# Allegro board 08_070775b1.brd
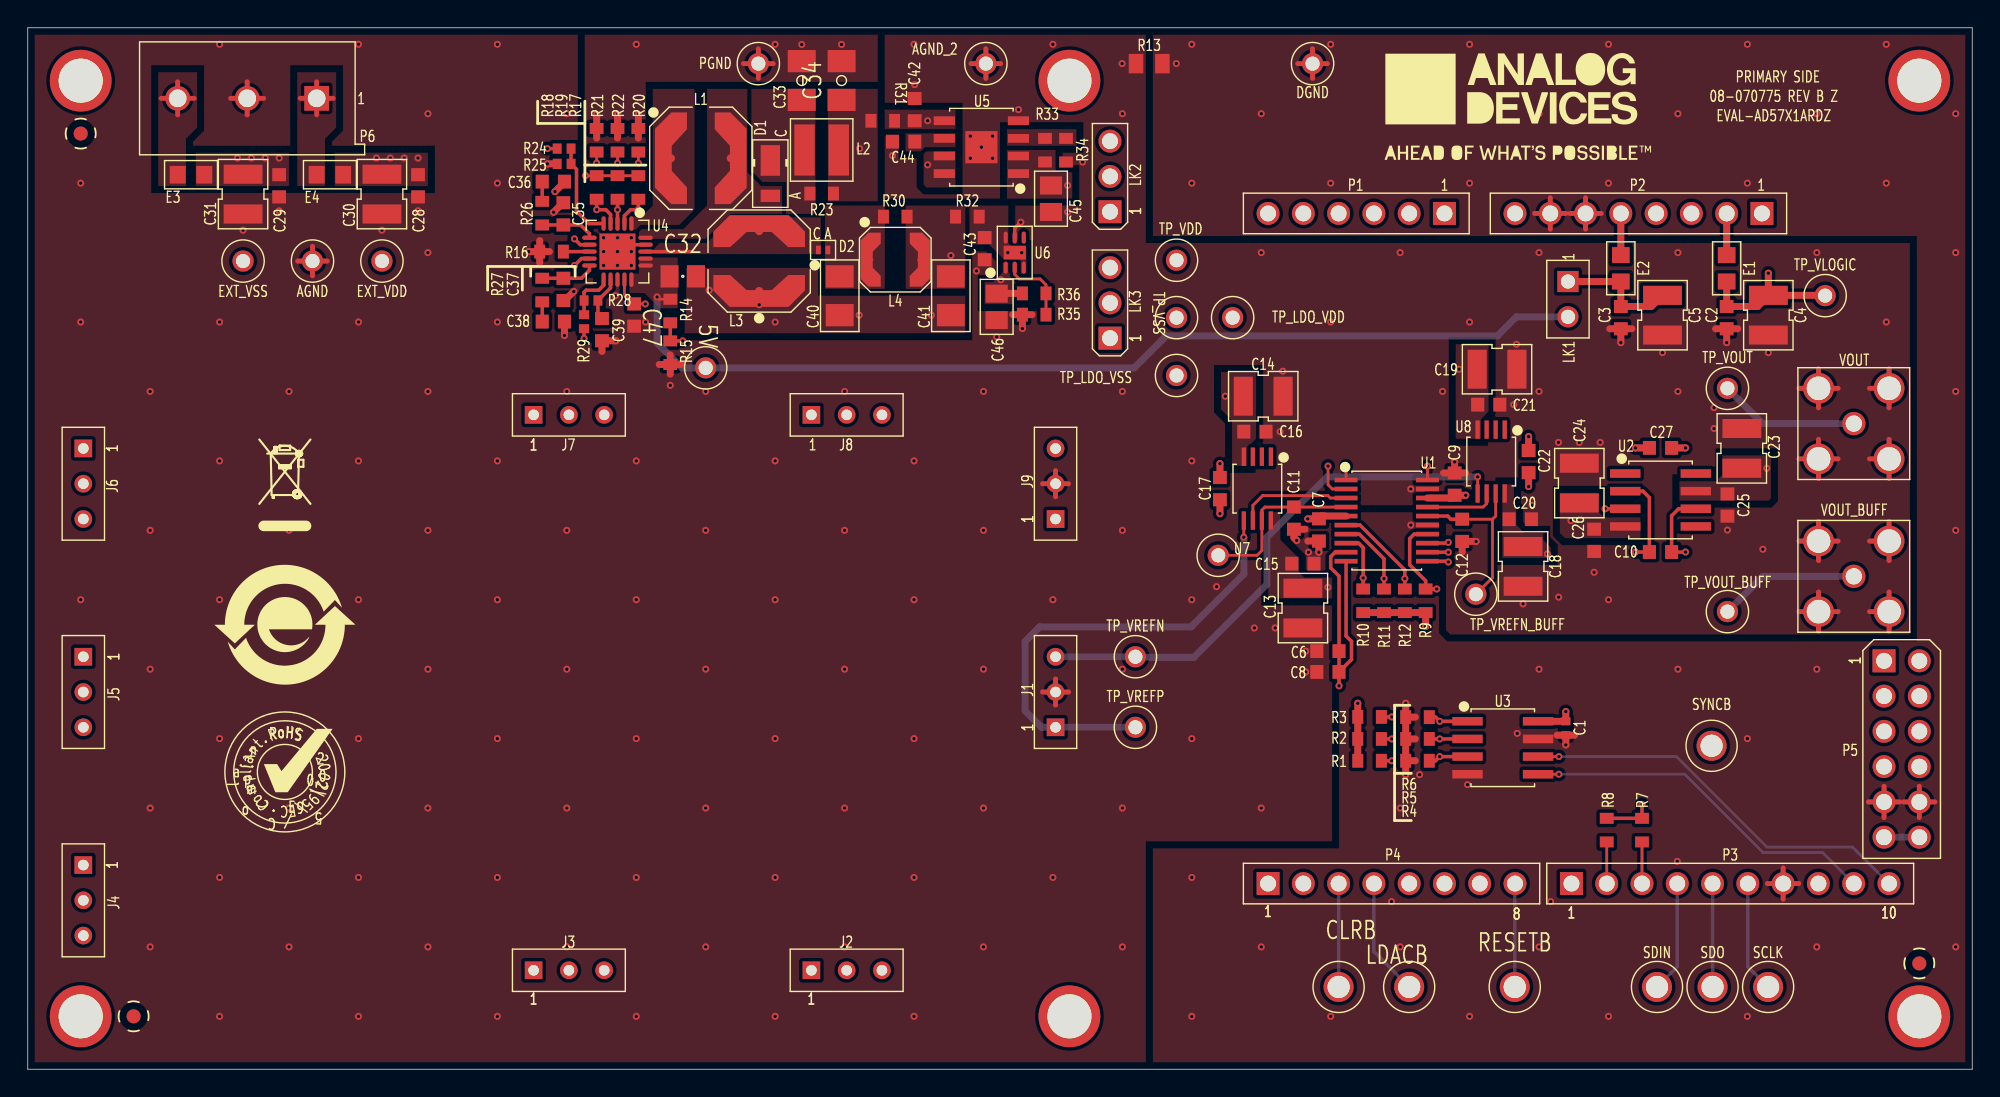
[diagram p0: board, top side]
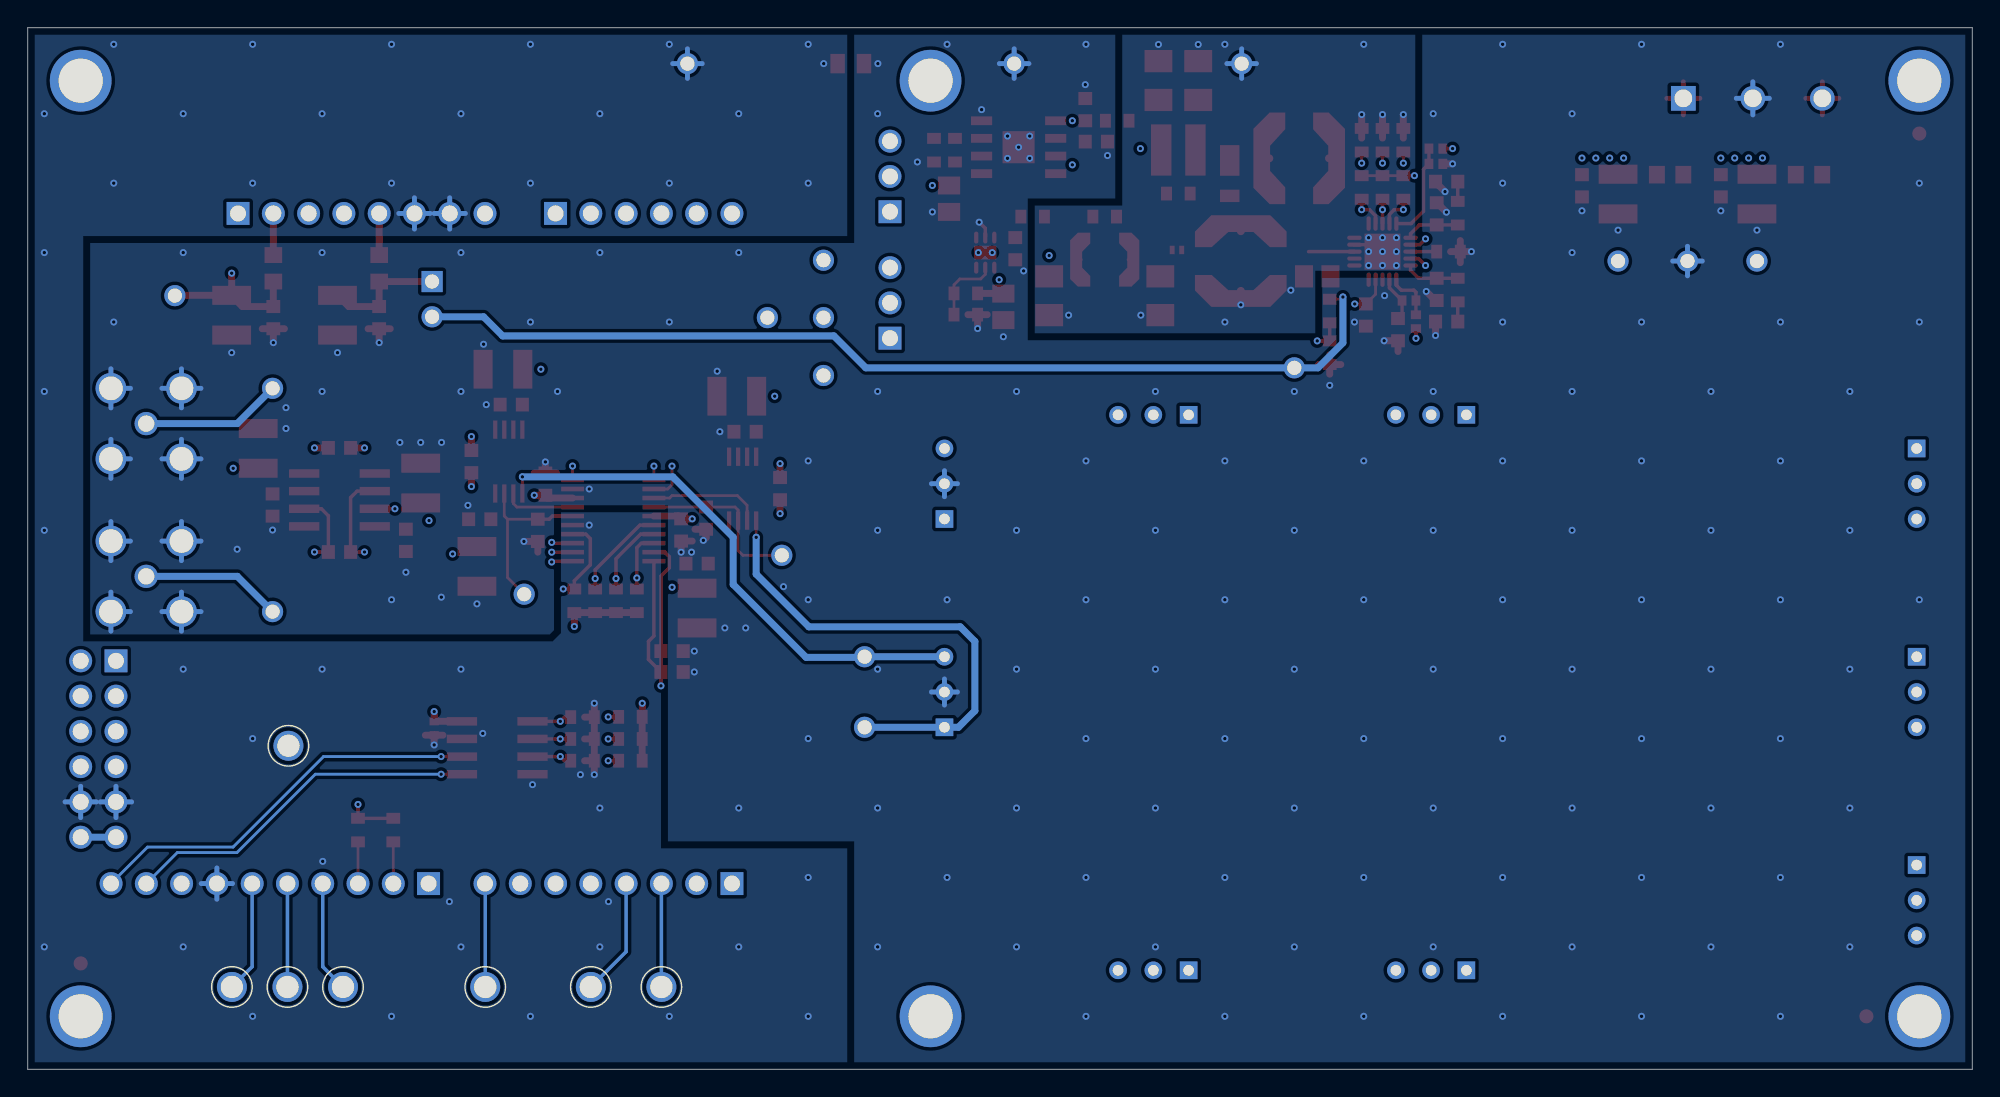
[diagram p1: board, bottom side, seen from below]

Outline 140 x 75 mm; copper layers: TOP, L2_GND, L3_SIG, L4_PWR, L5_GND, BOTTOM. Coordinates in mm from the lower left corner of the outline.
Outline path: 0,75 140,75 140,0 0,0 0,75

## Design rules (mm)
constraint set DEFAULT: 

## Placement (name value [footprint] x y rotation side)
C1  0.1uF  [C0402]  110.74 24.55 90 top
C2  0.1uF  [C0603]  122.32 54.12 270 top
C3  0.1uF  [C0603]  114.7 54.12 270 top
C4  10UF  [C1210H110]  125.32 54.3 270 top
C5  10UF  [C1210H110]  117.7 54.3 270 top
C6  0.1uF  [C0603]  93.61 30.11 180 top
C7  0.1uF  [C0603]  92.96 38.84 270 top
C8  0.1uF  [C0603]  93.61 28.61 180 top
C9  0.1uF  [C0603]  102.73 42.14 90 top
C10  10pF  [C0603]  117.56 37.25 180 top
C11  220pF  [C0603]  91.16 39.69 270 top
C12  220pF  [C0603]  103.28 38.81 270 top
C13  10UF  [C1210H110]  91.81 33.21 270 top
C14  10UF  [C1210H110]  88.95 48.47 180 top
C15  0.1uF  [C0603]  91.81 36.41 0 top
C16  0.1uF  [C0603]  88.36 45.91 180 top
C17  0.1uF  [C0603]  85.84 41.81 90 top
C18  10UF  [C1210H110]  107.66 36.21 270 top
C19  10UF  [C1210H110]  105.79 50.41 180 top
C20  0.1uF  [C0603]  107.46 39.61 0 top
C21  0.1uF  [C0603]  105.19 47.86 180 top
C22  0.1uF  [C0603]  108.06 43.76 90 top
C23  10UF  [C1210H110]  123.41 44.71 90 top
C24  10UF  [C1210H110]  111.71 42.21 270 top
C25  0.1uF  [C0603]  122.38 40.63 270 top
C26  0.1uF  [C0603]  112.78 38.09 90 top
C27  0.1uF  [C0603]  117.56 44.75 180 top
C28  0.1uF  [C0603]  28.1 63.62 270 top
C29  0.1uF  [C0603]  18.1 63.62 270 top
C30  10UF  [C1210H110]  25.5 63.02 270 top
C31  10UF  [C1210H110]  15.5 63.02 270 top
C32  10uF  [C0805H60]  47.16 57.1 0 top
C33  4.7uF  [C1206H71]  55.73 71.2 90 top
C34  4.7uF  [C1206H71]  58.59 71.2 90 top
C35  27pF  [C0603]  38.56 61.6 90 top
C36  0.022uF  [C0603]  37.84 63.92 0 top
C37  22pF  [C0603]  38.56 56.16 270 top
C38  0.082uF  [C0603]  37.84 53.84 0 top
C39  1UF  [C0603]  41.34 53.26 270 top
C40  2.2uF  [C1206H37]  58.46 55.7 270 top
C41  2.2uF  [C1206H37]  66.46 55.7 270 top
C42  1uF  [C0603]  63.86 69.11 90 top
C43  1uF  [C0603]  68.9 59.09 270 top
C44  0.01uF  [C0603]  63.06 66.8 180 top
C45  2.2uF  [C0805H53]  73.67 62.69 270 top
C46  2.2uF  [C0805H53]  69.76 54.9 270 top
C47  1uF  [C0603]  43.66 54.31 270 top
CLRB  WHT  [CNKEY5005-9TP]  94.38 5.93 0 top
D1  DFLS130-7  [POWERDI123]  53.46 64.5 270 top
D2  BAT54LPS  [DFN2_1X0_6]  57.26 59 0 top
E1  600OHM  [L0805H50]  122.32 57.68 270 top
E2  600OHM  [L0805H50]  114.7 57.68 270 top
E3  600OHM  [L0805H50]  11.75 64.42 0 top
E4  600OHM  [L0805H50]  21.75 64.42 0 top
J1  350-10-103-00-006000  [CNTHMHDR1X3L300W100H284]  74 24.62 90 top
J2  310-13-103-41-001000  [CNTHFHDR1X3L300W100H165]  56.42 7.12 0 top
J3  310-13-103-41-001000  [CNTHFHDR1X3L300W100H165]  36.42 7.12 0 top
J4  350-10-103-00-006000  [CNTHMHDR1X3L300W100H284]  4 14.71 270 top
J5  310-13-103-41-001000  [CNTHFHDR1X3L300W100H165]  4 29.7 270 top
J6  310-13-103-41-001000  [CNTHFHDR1X3L300W100H165]  4 44.71 270 top
J7  310-13-103-41-001000  [CNTHFHDR1X3L300W100H165]  36.42 47.12 0 top
J8  350-10-103-00-006000  [CNTHMHDR1X3L300W100H284]  56.42 47.12 0 top
J9  310-13-103-41-001000  [CNTHFHDR1X3L300W100H165]  74 39.62 90 top
L1  15uH  [LSMSQ236H138]  48.46 65.6 0 top
L2  1.5uH  [LSMSQ157H83]  57.16 66.2 0 top
L3  6.8uH  [LSMSQ236H138]  52.66 58.2 90 top
L4  2.2UH  [LSMSQ154H71_A]  62.46 58.3 0 top
LDACB  WHT  [CNKEY5005-9TP]  99.46 5.93 0 top
LK1  69157-102HLF  [CNBERG69157-102]  110.89 56.73 270 top
LK2  TSW-103-08-G-S  [CNBERG1X3H205LD36]  77.92 61.76 90 top
LK3  TSW-103-08-G-S  [CNBERG1X3H205LD36]  77.92 52.65 90 top
NOREF  -  []  18.51 32.01 0 top
NOREF#2  -  []  134 13.37 180 top
NOREF#3  -  []  -10.17 228.03 0 top
NOREF#4  -  [unnamed#2]  75 3.81 0 top
NOREF#5  -  [unnamed#2]  3.81 3.81 0 top
NOREF#6  -  []  3.81 3.81 0 top
NOREF#7  -  []  -22.36 -50.33 0 top
NOREF#8  -  []  3.81 3.81 0 top
NOREF#9  -  [unnamed#2]  3.81 71.19 0 top
NOREF#10  -  []  140 0 90 top
NOREF#11  -  []  212.02 314.24 0 top
NOREF#12  -  []  0 75 0 top
NOREF#13  -  []  0 0 0 top
NOREF#14  -  []  15 -82 0 top
NOREF#15  -  []  76.75 90.75 0 top
NOREF#16  -  []  18.31 38.81 0 top
NOREF#17  -  []  15 -82 0 top
NOREF#18  -  []  36.42 47.12 180 top
NOREF#19  -  []  -22.36 -50.33 0 top
NOREF#20  -  [unnamed#2]  75 71.19 0 top
NOREF#21  -  []  140 0 0 top
NOREF#22  -  [unnamed#2]  3.81 67.38 0 top
NOREF#23  -  []  88.21 167.82 0 top
NOREF#24  -  []  -2.99 312.45 0 top
NOREF#25  -  []  76.21 73.31 0 top
NOREF#26  -  [unnamed#2]  136.19 71.19 0 top
NOREF#27  -  [unnamed#2]  136.19 7.62 0 top
NOREF#28  -  []  140 0 0 top
NOREF#29  -  []  18.51 21.41 0 top
NOREF#30  -  []  140 75 0 top
NOREF#31  -  [unnamed#2]  136.19 3.81 0 top
NOREF#32  -  []  107.31 69.31 0 top
NOREF#33  -  [unnamed#2]  7.62 3.81 0 top
P1  SSQ-106-03-G-S  [CNSAMTECSSQ-106-XX-X-S]  102 61.63 180 top
P2  SSQ-108-03-G-S  [CNSAMTECSSQ-108-XX-X-S]  124.86 61.63 180 top
P3  SSQ-110-03-G-S  [CNSAMTECSSQ-110-XX-X-S]  111.14 13.37 0 top
P4  SSQ-108-03-G-S  [CNSAMTECSSQ-108-XX-X-S]  89.3 13.37 0 top
P5  TSW-106-08-G-D  [CNHDR2X6H330LD35]  133.65 29.41 270 top
P6  8719  [CNKEYSTONE-8719]  20.8 69.92 180 top
R1  100K  [R0603]  96.61 22.21 0 top
R2  0  [R0603]  96.61 23.79 0 top
R3  0  [R0603]  96.61 25.37 0 top
R4  0  [R0603]  100.06 22.21 180 top
R5  100K  [R0603]  100.06 23.79 180 top
R6  100K  [R0603]  100.06 25.36 180 top
R7  0  [R0603]  116.22 17.22 90 top
R8  0  [R0603]  113.68 17.22 90 top
R9  10K  [R0603]  100.65 33.73 90 top
R10  10K  [R0603]  96.15 33.73 90 top
R11  10K  [R0603]  97.65 33.73 90 top
R12  10K  [R0603]  99.15 33.73 90 top
R13  0  [R0805]  80.74 72.42 0 top
R14  30.1K  [R0603]  46.26 54.6 90 top
R15  18.7K  [R0603]  46.26 51.6 90 top
R16  49.9K  [R0603]  37.71 58.88 0 top
R17  0  [R0603]  43.96 63.5 270 top
R18  0  [R0603]  40.96 63.5 270 top
R19  0  [R0603]  42.46 63.5 270 top
R20  0  [R0603]  43.96 66.9 90 top
R21  0  [R0603]  40.96 66.9 90 top
R22  0  [R0603]  42.46 66.9 90 top
R23  4.7  [R0603]  57.16 63.06 0 top
R24  63.4K  [R0402]  38.62 66.3 180 top
R25  3.57K  [R0402]  38.62 65.2 180 top
R26  22K  [R0603]  37.04 61.65 90 top
R27  30.1K  [R0603]  37.04 56.11 270 top
R28  2.8K  [R0402]  40.55 55.36 180 top
R29  54.9K  [R0402]  40.05 53.84 270 top
R30  10  [R0603]  62.46 61.4 0 top
R31  10  [R0603]  61.56 68.31 0 top
R32  10  [R0603]  67.65 61.4 0 top
R33  105K  [R0603]  73.24 66.19 90 top
R34  10K  [R0603]  74.75 66.19 270 top
R35  10K  [R0603]  72.46 54.34 0 top
R36  105K  [R0603]  72.46 55.87 180 top
RESETB  WHT  [CNKEY5005-9TP]  107.06 5.93 0 top
SCLK  WHT  [CNKEY5005-9TP]  125.3 5.93 0 top
SDIN  WHT  [CNKEY5005-9TP]  117.3 5.93 0 top
SDO  WHT  [CNKEY5005-9TP]  121.3 5.93 0 top
SYNCB  WHT  [CNKEY5005-9TP]  121.23 23.29 0 top
TP_5V  RED  [CNKEY5001TP]  48.81 50.51 0 top
TP_AGND  BLK  [CNKEY5001TP]  20.5 58.2 0 top
TP_AGND2  BLK  [CNKEY5001TP]  68.98 72.42 0 top
TP_DGND  BLK  [CNKEY5001TP]  92.5 72.42 0 top
TP_EXT_VDD  RED  [CNKEY5001TP]  25.5 58.2 0 top
TP_EXT_VSS  RED  [CNKEY5001TP]  15.5 58.2 0 top
TP_LDO_VDD  RED  [CNKEY5001TP]  86.75 54.12 0 top
TP_LDO_VSS  RED  [CNKEY5001TP]  82.71 49.96 0 top
TP_PGND  BLK  [CNKEY5001TP]  52.6 72.42 0 top
TP_VDD  RED  [CNKEY5001TP]  82.71 58.26 0 top
TP_VLOGIC  RED  [CNKEY5001TP]  129.41 55.71 0 top
TP_VOUT  RED  [CNKEY5001TP]  122.38 49.04 0 top
TP_VOUT_BUFF  RED  [CNKEY5001TP]  122.38 32.95 0 top
TP_VREFN  RED  [CNKEY5001TP]  79.75 29.7 0 top
TP_VREFN_BUFF  RED  [CNKEY5001TP]  104.26 34.21 0 top
TP_VREFP  RED  [CNKEY5001TP]  79.75 24.62 0 top
TP_VREFP_BUFF  RED  [CNKEY5001TP]  85.71 37.01 0 top
TP_VSS  RED  [CNKEY5001TP]  82.71 54.12 0 top
U1  AD5781BRUZ  [TSSOP20]  97.85 39.51 270 top
U2  AD8675ARZ  [SO8]  117.56 41 270 top
U3  24AA32A-I/SN  [SO8]  106.2 23.15 270 top
U4  ADP5070ACPZ-R7  [QFN20_4X4_PAD2_6X2_6]  42.46 58.88 180 top
U5  ADP7118ARDZ  [SO8NB-PAD2_3X2_3]  68.66 66.4 90 top
U6  ADP7182ACPZN  [DFN6_2X2_PAD1_6X1]  71.06 58.81 0 top
U7  AD8676BRMZ  [MSOP8]  88.53 41.81 180 top
U8  AD8676BRMZ  [MSOP8]  105.37 43.76 180 top
VOUT  131-3701-261  [CNJOHNSON131-3701-261]  131.47 46.5 0 top
VOUT_BUFF  131-3701-261  [CNJOHNSON131-3701-261]  131.47 35.49 0 top

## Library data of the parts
C1 = CAP: User Part Number: UPN; Tolerance: 10; alternate symbols: (C0402); part number: CAP_SM-0.1UF,16V,10,E028141,C0402; tolerance: 10
C2 C3 C6-C9 C28 C29 = CAP: User Part Number: UPN; Tolerance: 10; alternate symbols: (C0603); part number: CAP_SM-0.1UF,16V,10,E015036,C0603; tolerance: 10
C4 C5 C13 C14 C18 C19 C23 C24 C30 C31 = CAP: Tolerance: 10; User Part Number: UPN; alternate symbols: (C1210H110); part number: CAP_SM-10UF,75V,10,E054052,C1210H110; tolerance: 10
C10 = CAP: User Part Number: UPN; Tolerance: 5; alternate symbols: (C0603); part number: CAP_SM-10PF,50V,5,E031564,C0603; tolerance: 5
C11 C12 = CAP: User Part Number: UPN; Tolerance: 5; alternate symbols: (C0603); part number: CAP_SM-220PF,50V,5,E000417,C0603; tolerance: 5
C15-C17 C20-C22 C25-C27 = CAP: User Part Number: UPN; Tolerance: 10; alternate symbols: (C0603); part number: CAP_SM-0.1UF,25V,10,E007204,C0603; tolerance: 10
C32 = CAP: Tolerance: 10; User Part Number: UPN; alternate symbols: (C0805H60); part number: CAP_SM-10UF,25V,10,E026259,C0805H60; tolerance: 10
C33 C34 = CAP: Tolerance: 10; User Part Number: UPN; alternate symbols: (C1206H71); part number: CAP_SM-4.7UF,50V,10,E038262,C1206H71; tolerance: 10
C35 = CAP: User Part Number: UPN; Tolerance: 5; alternate symbols: (C0603); part number: CAP_SM-27PF,50V,5,E000395,C0603; tolerance: 5
C36 = CAP: User Part Number: UPN; Tolerance: 10; alternate symbols: (C0603); part number: CAP_SM-0.022UF,16V,10,E000327,C0603; tolerance: 10
C37 = CAP: User Part Number: UPN; Tolerance: 5; alternate symbols: (C0603); part number: CAP_SM-22PF,50V,5,E000411,C0603; tolerance: 5
C38 = CAP: User Part Number: UPN; Tolerance: 10; alternate symbols: (C0603); part number: CAP_SM-0.082UF,16V,10,E028750,C0603; tolerance: 10
C39 = CAP: User Part Number: UPN; Tolerance: 20; alternate symbols: (C0603); part number: CAP_SM-1UF,10V,20,E042691,C0603; tolerance: 20
C40 C41 = CAP: Tolerance: 10; User Part Number: UPN; alternate symbols: (C1206H37); part number: CAP_SM-2.2UF,50V,10,E020593,C1206H37; tolerance: 10
C42 C43 = CAP: User Part Number: UPN; Tolerance: 10; alternate symbols: (C0603); part number: CAP_SM-1UF,16V,10,E020596,C0603; tolerance: 10
C44 = CAP: User Part Number: UPN; Tolerance: 10; alternate symbols: (C0603); part number: CAP_SM-0.01UF,50V,10,E015579,C0603; tolerance: 10
C45 C46 = CAP: Tolerance: 10; User Part Number: UPN; alternate symbols: (C0805H53); part number: CAP_SM-2.2UF,25V,10,E025703,C0805H53; tolerance: 10
C47 = CAP: User Part Number: UPN; Tolerance: 10; alternate symbols: (C0603); part number: CAP_SM-1UF,16V,10,E025399,C0603; tolerance: 10
CLRB LDACB RESETB SCLK SDIN SDO SYNCB = CNTP1P: Tolerance: N/A; User Part Number: UPN; alternate symbols: (CNKEY5005-9TP); part number: CNTP1P_TH-WHT,E025331,CNKEY5005-9TP; tolerance: N/A
D1 = DIOSCHOTTKY: User Part Number: UPN; Tolerance: N/A; alternate symbols: (POWERDI123); part number: DIOSCHOTTKY_SM-DFLS130-7,30V,N/A,E026485,POWERDI123; tolerance: N/A
D2 = DIOSCHOTTKY: Tolerance: N/A; User Part Number: UPN; alternate symbols: (DFN2_1X0_6); part number: DIOSCHOTTKY_SM-BAT54LPS,30V,N/A,E023691,DFN2_1X0_6; tolerance: N/A
E1-E4 = FERRITE: Tolerance: 25; User Part Number: UPN; alternate symbols: (L0805H50); part number: FERRITE_SM-600OHM,25,E013538,L0805H50; tolerance: 25
J1 J4 J8 = CN3P: User Part Number: UPN; Tolerance: N/A; alternate symbols: (CNTHMHDR1X3L300W100H284); part number: CN3P_TH-350-10-103-00-006000,E027762,CNTHMHDR1X3L300W100H284; tolerance: N/A
J2 J3 J5-J7 J9 = CN3P: User Part Number: UPN; Tolerance: N/A; alternate symbols: (CNTHFHDR1X3L300W100H165); part number: CN3P_TH-310-13-103-41-001000,E027752,CNTHFHDR1X3L300W100H165; tolerance: N/A
L1 = IND_SM-15UH,20,E019587,LSMSQ236H138-LSMSQ236H138: User Part Number: UPN; Tolerance: 20
L2 = IND: User Part Number: UPN; Tolerance: 20; alternate symbols: (LSMSQ157H83); part number: IND_SM-1.5UH,20,E017267,LSMSQ157H83; tolerance: 20
L3 = IND: User Part Number: UPN; Tolerance: 20; alternate symbols: (LSMSQ236H138); part number: IND_SM-6.8UH,20,E020918,LSMSQ236H138; tolerance: 20
L4 = IND: User Part Number: UPN; Tolerance: 20; alternate symbols: (LSMSQ154H71_A); part number: IND_SM-2.2UH,20,E024446,LSMSQ154H71_A; tolerance: 20
LK1 = CN2P: User Part Number: UPN; Tolerance: N/A; alternate symbols: (CNBERG69157-102); part number: CN2P_TH-69157-102HLF,E000791,CNBERG69157-102; tolerance: N/A
LK2 LK3 = CN3P: User Part Number: UPN; Tolerance: N/A; alternate symbols: (CNBERG1X3H205LD36); part number: CN3P_TH-TSW-103-08-G-S,E000812,CNBERG1X3H205LD36; tolerance: N/A
P1 = CN6P: User Part Number: UPN; Tolerance: N/A; alternate symbols: (CNSAMTECSSQ-106-XX-X-S); part number: CN6P_TH-SSQ-106-03-G-S,E020477,CNSAMTECSSQ-106-XX-X-S; tolerance: N/A
P2 P4 = CN8P_A: User Part Number: UPN; Tolerance: N/A; alternate symbols: (CNSAMTECSSQ-108-XX-X-S); part number: CN8P_A_TH-SSQ-108-03-G-S,E020478,CNSAMTECSSQ-108-XX-X-S; tolerance: N/A
P3 = CN10P: User Part Number: UPN; Tolerance: N/A; alternate symbols: (CNSAMTECSSQ-110-XX-X-S); part number: CN10P_TH-SSQ-110-03-G-S,E020479,CNSAMTECSSQ-110-XX-X-S; tolerance: N/A
P5 = CN12P_V3: Tolerance: N/A; User Part Number: UPN; alternate symbols: (CNHDR2X6H330LD35); part number: CN12P_V3_TH-TSW-106-08-G-D,E000735,CNHDR2X6H330LD35; tolerance: N/A
P6 = CN3P: Tolerance: N/A; User Part Number: UPN; alternate symbols: (CNKEYSTONE-8719); part number: CN3P_TH-8719,E023615,CNKEYSTONE-8719; tolerance: N/A
R1 R5 R6 = RES: User Part Number: UPN; Tolerance: 1; alternate symbols: (R0603); part number: RES_SM-100K,E017869,1/10W,1,R0603; tolerance: 1
R2-R4 = RES: User Part Number: UPN; Tolerance: 1; alternate symbols: (R0603); part number: RES_SM-0,E004207,1/16W,1,R0603; tolerance: 1
R7 R8 R17-R22 = RES: User Part Number: UPN; Tolerance: JUMPER; alternate symbols: (R0603); part number: RES_SM-0,E054377,1/10W,JUMPER,R0603; tolerance: JUMPER
R9-R12 = RES: User Part Number: UPN; Tolerance: 0.1; alternate symbols: (R0603); part number: RES_SM-10K,E020748,1/10W,0.1,R0603; tolerance: 0.1
R13 = RES: User Part Number: UPN; Tolerance: N/A; alternate symbols: (R0805); part number: RES_SM-0,E004449,1/8W,N/A,R0805; tolerance: N/A
R14 R27 = RES: User Part Number: UPN; Tolerance: 1; alternate symbols: (R0603); part number: RES_SM-30.1K,E011129,1/10W,1,R0603; tolerance: 1
R15 = RES: User Part Number: UPN; Tolerance: 1; alternate symbols: (R0603); part number: RES_SM-18.7K,E011248,1/10W,1,R0603; tolerance: 1
R16 = RES: User Part Number: UPN; Tolerance: 1; alternate symbols: (R0603); part number: RES_SM-49.9K,E015342,1/10W,1,R0603; tolerance: 1
R23 = RES: User Part Number: UPN; Tolerance: 1; alternate symbols: (R0603); part number: RES_SM-4.7,E003938,1/10W,1,R0603; tolerance: 1
R24 = RES: User Part Number: UPN; Tolerance: 1; alternate symbols: (R0402); part number: RES_SM-63.4K,E006803,1/10W,1,R0402; tolerance: 1
R25 = RES: User Part Number: UPN; Tolerance: 1; alternate symbols: (R0402); part number: RES_SM-3.57K,E007344,1/10W,1,R0402; tolerance: 1
R26 = RES: User Part Number: UPN; Tolerance: 0.1; alternate symbols: (R0603); part number: RES_SM-22K,E057217,1/5W,0.1,R0603; tolerance: 0.1
R28 = RES: User Part Number: UPN; Tolerance: 1; alternate symbols: (R0402); part number: RES_SM-2.8K,E012202,1/10W,1,R0402; tolerance: 1
R29 = RES: User Part Number: UPN; Tolerance: 1; alternate symbols: (R0402); part number: RES_SM-54.9K,E023190,1/10W,1,R0402; tolerance: 1
R30-R32 = RES: User Part Number: UPN; Tolerance: 1; alternate symbols: (R0603); part number: RES_SM-10,E003666,1/10W,1,R0603; tolerance: 1
R33 R36 = RES: User Part Number: UPN; Tolerance: 1; alternate symbols: (R0603); part number: RES_SM-105K,E019711,1/10W,1,R0603; tolerance: 1
R34 R35 = RES: User Part Number: UPN; Tolerance: 1; alternate symbols: (R0603); part number: RES_SM-10K,E003671,1/10W,1,R0603; tolerance: 1
TP_5V TP_EXT_VDD TP_EXT_VSS TP_LDO_VDD TP_LDO_VSS TP_VDD TP_VLOGIC TP_VOUT TP_VOUT_BUFF TP_VREFN TP_VREFN_BUFF TP_VREFP TP_VREFP_BUFF TP_VSS = CNTP1P: Tolerance: N/A; User Part Number: UPN; alternate symbols: (CNKEY5001TP); part number: CNTP1P_TH-RED,E016323,CNKEY5001TP; tolerance: N/A
TP_AGND TP_AGND2 TP_DGND TP_PGND = CNTP1P: Tolerance: N/A; User Part Number: UPN; alternate symbols: (CNKEY5001TP); part number: CNTP1P_TH-BLK,E005347,CNKEY5001TP; tolerance: N/A
U1 = AD5781: Tolerance: N/A; User Part Number: UPN; alternate symbols: (TSSOP20); part number: AD5781_SM-AD5781BRUZ,E016086,TSSOP20; tolerance: N/A
U2 = AD8675: Tolerance: N/A; User Part Number: UPN; alternate symbols: (SO8); part number: AD8675_SM-AD8675ARZ,E005913,SO8; tolerance: N/A
U3 = IC24XX32A_V2: Tolerance: N/A; User Part Number: UPN; alternate symbols: (SO8); part number: IC24XX32A_V2_SM-24AA32A-I/SN,E034913,SO8; tolerance: N/A
U4 = ADP5070: User Part Number: UPN; Tolerance: N/A; alternate symbols: (QFN20_4X4_PAD2_6X2_6); part number: ADP5070_SM-ADP5070ACPZ-R7,E017319,QFN20_4X4_PAD2_6X2_6; tolerance: N/A
U5 = ADP7118_V3: Tolerance: N/A; User Part Number: UPN; alternate symbols: (SO8NB-PAD2_3X2_3); part number: ADP7118_V3_SM-ADP7118ARDZ,E020780,SO8NB-PAD2_3X2_3; tolerance: N/A
U6 = ADP7182_V5: User Part Number: UPN; Tolerance: N/A; alternate symbols: (DFN6_2X2_PAD1_6X1); part number: ADP7182_V5_SM-ADP7182ACPZN,E024308,DFN6_2X2_PAD1_6X1; tolerance: N/A
U7 U8 = ADOPAMP2: Tolerance: N/A; User Part Number: UPN; alternate symbols: (MSOP8); part number: ADOPAMP2_SM-AD8676BRMZ,E015333,MSOP8; tolerance: N/A
VOUT VOUT_BUFF = CNBNC5P: Tolerance: N/A; User Part Number: UPN; alternate symbols: (CNJOHNSON131-3701-261); part number: CNBNC5P_TH-131-3701-261,E012123,CNJOHNSON131-3701-261; tolerance: N/A

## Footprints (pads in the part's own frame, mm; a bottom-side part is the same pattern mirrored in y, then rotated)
C0402
  rect 0.584x0.66 smd: 1(-0.5,0) 2(0.5,0)
C0603
  rect 0.94x0.991 smd: 1(-0.8,0) 2(0.8,0)
C0805H53
  rect 1.295x1.6 smd: 1(-0.953,0) 2(0.953,0)
C0805H60
  rect 1.295x1.6 smd: 1(-0.953,0) 2(0.953,0)
C1206H37
  rect 1.6x2.007 smd: 1(-1.397,0) 2(1.397,0)
C1206H71
  rect 1.6x2.007 smd: 1(-1.397,0) 2(1.397,0)
C1210H110
  rect 1.372x2.794 smd: 1(-1.431,0) 2(1.431,0)
CNBERG1X3H205LD36
  rect 1.651x1.651 hole 1.143: 1(0,0)
  round 1.651 hole 1.143: 2(2.54,0) 3(5.08,0)
CNBERG69157-102
  rect 1.524x1.524 hole 1.016: 1(0,0)
  round 1.524 hole 1.016: 2(2.54,0)
CNHDR2X6H330LD35
  rect 1.651x1.651 hole 1.143: 1(0,0)
  round 1.651 hole 1.143: 2(2.54,0) 3(5.08,0) 4(7.62,0) 5(10.16,0) 6(12.7,0) 7(0,2.54) 8(2.54,2.54) 9(5.08,2.54) 10(7.62,2.54) 11(10.16,2.54) 12(12.7,2.54)
CNJOHNSON131-3701-261
  round 1.676 hole 1.168: 1(0,0)
  round 2.21 hole 1.702: 2(-2.54,2.54) 3(2.54,2.54) 4(2.54,-2.54) 5(-2.54,-2.54)
CNKEY5001TP
  round 1.524 hole 1.016: 1(0,0)
CNKEY5005-9TP
  round 2.159 hole 1.6: 1(0,0)
CNKEYSTONE-8719
  rect 1.778x1.778 hole 1.27: 1(0,0)
  round 1.778 hole 1.27: 2(5.004,0) 3(10.008,0)
CNSAMTECSSQ-106-XX-X-S
  rect 1.651x1.651 hole 1.143: 1(0,0)
  round 1.651 hole 1.143: 2(2.54,0) 3(5.08,0) 4(7.62,0) 5(10.16,0) 6(12.7,0)
CNSAMTECSSQ-108-XX-X-S
  rect 1.651x1.651 hole 1.143: 1(0,0)
  round 1.651 hole 1.143: 2(2.54,0) 3(5.08,0) 4(7.62,0) 5(10.16,0) 6(12.7,0) 7(15.24,0) 8(17.78,0)
CNSAMTECSSQ-110-XX-X-S
  rect 1.651x1.651 hole 1.143: 1(0,0)
  round 1.651 hole 1.143: 2(2.54,0) 3(5.08,0) 4(7.62,0) 5(10.16,0) 6(12.7,0) 7(15.24,0) 8(17.78,0) 9(20.32,0) 10(22.86,0)
CNTHFHDR1X3L300W100H165
  rect 1.27x1.27 hole 0.762: 1(0,0)
  round 1.27 hole 0.762: 2(2.54,0) 3(5.08,0)
CNTHMHDR1X3L300W100H284
  rect 1.27x1.27 hole 0.762: 1(0,0)
  round 1.27 hole 0.762: 2(2.54,0) 3(5.08,0)
DFN2_1X0_6
  rect 0.356x0.61 smd: A(0.34,0) C(-0.34,0)
DFN6_2X2_PAD1_6X1
  oval 0.305x0.864 smd: 1(-0.65,-1.082) 2(0,-1.082) 3(0.65,-1.082) 4(0.65,1.082) 5(0,1.082) 6(-0.65,1.082)
  rect 1.6x0.991 smd: PAD(0,0)
L0805H50
  rect 1.143x1.27 smd: 1(-0.953,0) 2(0.953,0)
LSMSQ154H71_A
  custom 0.362x0.362 smd: 1(-1.765,0) 2(1.765,0)
LSMSQ157H83
  rect 1.473x3.683 smd: 1(-1.232,0) 2(1.232,0)
LSMSQ236H138
  custom 0.575x0.575 smd: 1(-2.151,0) 2(2.151,0)
MSOP8
  rect 0.305x1.321 smd: 1(-0.975,-2.3) 2(-0.325,-2.3) 3(0.325,-2.3) 4(0.975,-2.3) 5(0.975,2.3) 6(0.325,2.3) 7(-0.325,2.3) 8(-0.975,2.3)
POWERDI123
  rect 0.889x1.397 smd: A(1.605,0)
  rect 2.21x1.397 smd: C(-0.945,0)
QFN20_4X4_PAD2_6X2_6
  oval 0.305x1.041 smd: 1(-1,-2.019) 2(-0.5,-2.019) 3(0,-2.019) 4(0.5,-2.019) 5(1,-2.019) 11(1,2.019) 12(0.5,2.019) 13(0,2.019) 14(-0.5,2.019) 15(-1,2.019)
  oval 1.041x0.305 smd: 6(2.019,-1) 7(2.019,-0.5) 8(2.019,0) 9(2.019,0.5) 10(2.019,1) 16(-2.019,1) 17(-2.019,0.5) 18(-2.019,0) 19(-2.019,-0.5) 20(-2.019,-1)
  rect 2.591x2.591 smd: PAD(0,0)
R0402
  rect 0.635x0.737 smd: 1(-0.5,0) 2(0.5,0)
R0603
  rect 0.787x0.991 smd: 1(-0.85,0) 2(0.85,0)
R0805
  rect 1.041x1.397 smd: 1(-0.95,0) 2(0.95,0)
SO8
  rect 0.61x2.184 smd: 1(-1.905,-2.54) 2(-0.635,-2.54) 3(0.635,-2.54) 4(1.905,-2.54) 5(1.905,2.54) 6(0.635,2.54) 7(-0.635,2.54) 8(-1.905,2.54)
SO8NB-PAD2_3X2_3
  rect 0.635x1.524 smd: 1(-1.905,-2.667) 2(-0.635,-2.667) 3(0.635,-2.667) 4(1.905,-2.667) 5(1.905,2.667) 6(0.635,2.667) 7(-0.635,2.667) 8(-1.905,2.667)
  rect 2.311x2.311 smd: PAD(0,0)
TSSOP20
  rect 0.33x1.651 smd: 1(-2.925,-2.93) 2(-2.275,-2.93) 3(-1.625,-2.93) 4(-0.975,-2.93) 5(-0.325,-2.93) 6(0.325,-2.93) 7(0.975,-2.93) 8(1.625,-2.93) 9(2.275,-2.93) 10(2.925,-2.93) 11(2.925,2.93) 12(2.275,2.93) 13(1.625,2.93) 14(0.975,2.93) 15(0.325,2.93) 16(-0.325,2.93) 17(-0.975,2.93) 18(-1.625,2.93) 19(-2.275,2.93) 20(-2.925,2.93)
unnamed#2
  round 4.445 hole 3.175 unplated: (0,0)

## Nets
AGND: C2.2(N2) C3.2(N2) C4.2(N2) C5.2(N2) C6.2(N2) C7.2(N2) C8.2(N2) C9.2(N2) C11.2(N2) C12.2(N2) C13.2(N2) C14.1 C15.2(N2) C16.1 C18.2(N2) C19.1 C20.2(N2) C21.1 C23.2(N2) C24.1 C25.2(N2) C26.1 C28.2(N2) C29.2(N2) C30.2(N2) C31.2(N2) C32.2(N2) C33.2(N2) C34.2(N2) C35.2(N2) C36.2(N2) C37.2(N2) C38.2(N2) C39.2(N2) C40.2(N2) C41.2(N2) C42.2(N2) C43.2(N2) C44.2(N2) C45.2(N2) C46.2(N2) C47.2(N2) J1.2 J9.2 L3.1 P6.2 R13.1 R15.1 R16.1 R20.2(N2) R21.2(N2) R22.2(N2) R25.2(N2) R34.2(N2) R35.1 TP_AGND.1(N1) TP_AGND2.1(N1) TP_PGND.1(N1) U1.19 U4.13 U4.19 U4.PAD U5.4 U5.PAD U6.5 VOUT.2 VOUT.3 VOUT.4 VOUT.5(SH4) VOUT_BUFF.2 VOUT_BUFF.3 VOUT_BUFF.4 VOUT_BUFF.5(SH4)
DGND: C1.1 P2.6 P2.7 P3.7 P5.5 P5.11 R4.2(N2) R5.2(N2) R6.2(N2) R13.2(N2) TP_DGND.1(N1) U1.15 U3.4 U3.7(WP)
VDD: C7.1 C13.1 C15.1 C17.1 C18.1 C20.1 C22.1 C23.1 C25.1 C27.1 J9.1 LK2.2 TP_VDD.1(N1) U1.5 U2.7 U7.8 U8.8
VSS: C9.1 C14.2(N2) C16.2(N2) C17.2(N2) C19.2(N2) C21.2(N2) C22.2(N2) C24.2(N2) C26.2(N2) C27.2(N2) J9.3(N3) LK3.2 TP_VSS.1(N1) U1.18(VSS) U2.4(V-) U7.4(V-) U8.4(V-)
ARD_5V: C32.1 LK1.2(N2) R14.2(N2) TP_5V.1(N1) U4.15 U4.16 U4.17
ARD_CLRB: CLRB.1(N1) P4.3 P5.9 R11.2(N2) U1.7
ARD_LDACB: LDACB.1(N1) P4.4 P5.7 R10.2(N2) U1.8
ARD_RESETB: P4.8(N8) P5.8 R12.2(N2) RESETB.1(N1) U1.6
ARD_SCL: P3.10 U3.6
ARD_SCLK: P3.6 P5.4 SCLK.1(N1) U1.13
ARD_SDA: P3.9(N9) U3.5
ARD_SDIN: P3.4 P5.2 SDIN.1(N1) U1.12
ARD_SDO: P3.5 P5.3 SDO.1(N1) U1.11
ARD_SYNCB: P5.1 R7.2(N2) R8.2(N2) R9.2(N2) SYNCB.1(N1) U1.14
ARD_VLOGIC: C1.2(N2) C2.1 C4.1 C6.1 C8.1 E1.2(N2) P5.6 P5.12(VCC2) R1.1 R2.1 R3.1 R9.1 R10.1 R11.1 R12.1 TP_VLOGIC.1(N1) U1.9 U1.10 U3.8
DAC_INV: C10.2(N2) U1.1 U2.2
DAC_VOUT: C10.1 TP_VOUT_BUFF.1(N1) U1.20 U2.6 VOUT_BUFF.1
EXT_VDD: C28.1 C30.1 E4.2(N2) LK2.3(N3) TP_EXT_VDD.1(N1)
EXT_VSS: C29.1 C31.1 E3.2(N2) LK3.3(N3) TP_EXT_VSS.1(N1)
LDO_VDD: C45.1 LK2.1 R33.1 TP_LDO_VDD.1(N1) U5.1 U5.2(VOUT2)
LDO_VSS: C46.1 LK3.1 R36.2(N2) TP_LDO_VSS.1(N1) U6.1(VOUT)
REF_VREFN: J1.3(N3) TP_VREFN.1(N1) U8.5
REF_VREFP: J1.1 TP_VREFP.1(N1) U7.5
UNNAMED_3_CAP_I64_N1: C3.1 C5.1 E2.2(N2) LK1.1
UNNAMED_3_CN8PA_I4_N2: E1.1 P2.2
UNNAMED_3_CN8PA_I4_N5: E2.1 P2.5
UNNAMED_3_CN10P_I1_N2: P3.2 R8.1
UNNAMED_3_CN10P_I1_N3: P3.3 R7.1
UNNAMED_3_IC24XX32AV2_I22_A0: R3.2(N2) R6.1 U3.1
UNNAMED_3_IC24XX32AV2_I22_A1: R2.2(N2) R5.1 U3.2
UNNAMED_3_IC24XX32AV2_I22_A2: R1.2(N2) R4.1 U3.3
UNNAMED_4_AD5781_I1_VOUT: TP_VOUT.1(N1) U1.2 U2.3 VOUT.1
UNNAMED_5_ADP5070_I35_COMP1: C35.1 R26.1 U4.6
UNNAMED_5_ADP5070_I35_COMP2: C37.1 R27.1 U4.10
UNNAMED_5_ADP5070_I35_EN1: R14.1 R15.2(N2) U4.7 U4.9
UNNAMED_5_ADP5070_I35_FB1: R24.1 R25.1 U4.5
UNNAMED_5_ADP5070_I35_FB2: R28.2(N2) R29.1 U4.11
UNNAMED_5_ADP5070_I35_INBK: L1.1 U4.1
UNNAMED_5_ADP5070_I35_SEQ: R19.2(N2) R22.1 U4.3
UNNAMED_5_ADP5070_I35_SLEW: R18.2(N2) R21.1 U4.4
UNNAMED_5_ADP5070_I35_SS: R16.2(N2) U4.8
UNNAMED_5_ADP5070_I35_SW1: D1.A(P) L1.2(N2) U4.20
UNNAMED_5_ADP5070_I35_SW2: D2.C L3.2(N2) U4.18
UNNAMED_5_ADP5070_I35_SYNC: R17.2(N2) R20.1 U4.2
UNNAMED_5_ADP5070_I35_VREF: C39.1 R28.1 U4.12
UNNAMED_5_ADP5070_I35_VREG: C47.1 R17.1 R18.1 R19.1 U4.14(VREG)
UNNAMED_5_ADP7118V3_I94_EN: C42.1 R31.2(N2) U5.5 U5.7 U5.8
UNNAMED_5_ADP7118V3_I94_SENSE: R33.2(N2) R34.1 U5.3
UNNAMED_5_ADP7118V3_I94_SS: C44.1 U5.6
UNNAMED_5_ADP7182V5_I95_ADJ: R35.2(N2) R36.1 U6.2
UNNAMED_5_ADP7182V5_I95_EN: C43.1 R32.2(N2) U6.3 U6.6 U6.PAD
UNNAMED_5_CAP_I60_N1: C33.1 D1.C L2.1 R23.1
UNNAMED_5_CAP_I61_N1: C34.1 L2.2(N2) R23.2(N2) R24.2(N2) R31.1
UNNAMED_5_CAP_I69_N1: C36.1 R26.2(N2)
UNNAMED_5_CAP_I73_N1: C38.1 R27.2(N2)
UNNAMED_5_CAP_I79_N1: C41.1 L4.2(N2) R29.2(N2) R30.2(N2) R32.1
UNNAMED_5_CAP_I80_N1: C40.1 D2.A(P) L4.1 R30.1
UNNAMED_5_CN3P_I3_N1: E4.1 P6.1
UNNAMED_5_CN3P_I3_N3: E3.1 P6.3(N3)
VREFNF: C12.1 TP_VREFN_BUFF.1(N1) U1.16 U8.7
VREFNS: U1.17 U8.6
VREFPF: C11.1 TP_VREFP_BUFF.1(N1) U1.4 U7.7
VREFPS: U1.3 U7.6

Pads without a net: J2 1 2 3; J3 1 2 3; J4 1 2 3; J5 1 2 3; J6 1 2 3; J7 1 2 3; J8 1 2 3; P1 1 2 3 4 5 6; P2 1 3 4 8; P3 1 8; P4 1 2 5 6 7; P5 10; U2 1 5 8; U6 4; U7 1 2 3; U8 1 2 3

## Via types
v1: diameter 0.508, hole 0.254, TOP to BOTTOM, 305 vias

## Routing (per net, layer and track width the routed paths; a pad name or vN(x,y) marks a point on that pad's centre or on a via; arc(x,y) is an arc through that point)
AGND: length 305.4
  TOP w0.25: U6.5 71.06,60.56 v1(71.5,61) ; U4.19 42.96,59.38 v1(42.46,58.88)
  TOP w0.35: 132.61,38.04 VOUT_BUFF.3 ; VOUT_BUFF.3 134.01,39.44 ; VOUT_BUFF.3 134.01,36.63 ; 127.53,43.96 VOUT.5 ; VOUT.5 128.93,45.36 ; VOUT.5 128.93,42.55 ; VOUT.5 130.34,43.96 ; J9.2 74,43.1 ; J9.2 73.06,42.16 ; J9.2 74.94,42.16 ; J9.2 74,41.23 ; TP_PGND.1 53.66,72.42 ; TP_PGND.1 51.54,72.42 ; TP_PGND.1 52.6,73.48 ; TP_PGND.1 52.6,71.36 ; TP_AGND.1 21.56,58.2 ; TP_AGND.1 20.5,59.26 ; TP_AGND.1 20.5,57.14 ; TP_AGND.1 19.44,58.2 ; VOUT.2 128.93,50.44 ; VOUT.2 127.53,49.04 ; VOUT.2 128.93,47.63 ; VOUT.2 130.34,49.04 ; VOUT_BUFF.2 128.93,39.44 ; VOUT_BUFF.2 130.34,38.04 ; VOUT_BUFF.2 127.53,38.04 ; VOUT_BUFF.2 128.93,36.63 ; 128.93,31.55 VOUT_BUFF.5 ; VOUT_BUFF.5 128.93,34.36 ; VOUT_BUFF.5 127.53,32.95 ; VOUT_BUFF.5 130.34,32.95 ; J1.2 74,28.1 ; J1.2 73.06,27.16 ; J1.2 74,26.23 ; J1.2 74.94,27.16 ; 134.01,42.55 VOUT.4 ; VOUT.4 134.01,45.36 ; VOUT.4 132.61,43.96 ; 134.01,47.63 VOUT.3 ; VOUT.3 132.61,49.04 ; VOUT.3 134.01,50.44 ; 15.8,68.73 P6.2 ; P6.2 14.61,69.92 ; P6.2 16.99,69.92 ; P6.2 15.8,71.11 ; TP_AGND2.1 68.98,73.48 ; TP_AGND2.1 70.05,72.42 ; TP_AGND2.1 67.92,72.42 ; TP_AGND2.1 68.98,71.36 ; 132.61,32.95 VOUT_BUFF.4 ; VOUT_BUFF.4 134.01,34.36 ; VOUT_BUFF.4 134.01,31.55
  TOP w0.5: R16.1 37.55,58.88 ; R16.1 36.86,59.68 ; R16.1 36.86,58.08 ; R16.1 v1(36.06,58.88) ; R25.2 v1(37.41,65.2) ; R35.1 72.31,54.34 ; R35.1 v1(71.61,53.34) ; R35.1 70.92,54.34 ; v1(104.28,38.01) C12.2 103.28,37.24 ; C3.2 115.5,53.33 ; C3.2 113.9,53.33 ; C3.2 v1(114.7,52.33) ; R15.1 45.46,50.75 ; R15.1 47.06,50.75 ; R15.1 46.26,50.06 ; R15.1 46.26,51.44 ; C35.2 38.54,62.4 v1(37.86,61.72) ; C2.2 123.12,53.33 ; C2.2 121.52,53.33 ; C2.2 v1(122.32,52.33) ; 41.34,51.69 C39.2 v1(42.34,52.46) ; 92.16,38.04 C7.2 v1(92.96,37.23) ; C37.2 38.66,55.36 v1(39.31,56.01) ; C36.2 38.64,63.88 v1(37.96,63.2) ; 42.46,67.06 R22.2 v1(42.46,68.75) ; C38.2 v1(38.64,52.84) ; 40.96,67.06 R21.2 v1(40.96,68.75) ; 91.96,38.89 C11.2 91.16,38.29 v1(91.36,38.09) ; C9.2 v1(102.73,43.73) ; C9.2 103.53,42.94 ; C9.2 101.94,42.94 ; 43.96,67.06 R20.2 v1(43.96,68.75)
  L2_GND w0.35: 128.93,31.55 VOUT_BUFF.5 ; VOUT_BUFF.5 127.53,32.95 ; VOUT_BUFF.5 130.34,32.95 ; VOUT_BUFF.5 128.93,34.36 ; 73.06,42.16 J9.2 ; J9.2 74.94,42.16 ; J9.2 74,43.1 ; J9.2 74,41.23 ; VOUT.3 134.01,50.44 ; VOUT.3 132.61,49.04 ; VOUT.3 134.01,47.63 ; J1.2 74,28.1 ; J1.2 74.94,27.16 ; J1.2 73.06,27.16 ; J1.2 74,26.23 ; TP_AGND2.1 70.05,72.42 ; TP_AGND2.1 68.98,71.36 ; TP_AGND2.1 67.92,72.42 ; TP_AGND2.1 68.98,73.48 ; VOUT.2 130.34,49.04 ; VOUT.2 128.93,47.63 ; VOUT.2 127.53,49.04 ; VOUT.2 128.93,50.44 ; TP_PGND.1 53.66,72.42 ; TP_PGND.1 52.6,73.48 ; TP_PGND.1 52.6,71.36 ; TP_PGND.1 51.54,72.42 ; VOUT_BUFF.4 134.01,34.36 ; VOUT_BUFF.4 134.01,31.55 ; VOUT_BUFF.4 132.61,32.95 ; TP_AGND.1 21.56,58.2 ; TP_AGND.1 19.44,58.2 ; TP_AGND.1 20.5,59.26 ; TP_AGND.1 20.5,57.14 ; 134.01,42.55 VOUT.4 ; VOUT.4 132.61,43.96 ; VOUT.4 134.01,45.36 ; P6.2 16.99,69.92 ; P6.2 15.8,68.73 ; P6.2 14.61,69.92 ; P6.2 15.8,71.11 ; 134.01,36.63 VOUT_BUFF.3 ; VOUT_BUFF.3 132.61,38.04 ; VOUT_BUFF.3 134.01,39.44 ; 127.53,38.04 VOUT_BUFF.2 ; VOUT_BUFF.2 128.93,36.63 ; VOUT_BUFF.2 130.34,38.04 ; VOUT_BUFF.2 128.93,39.44 ; 127.53,43.96 VOUT.5 ; VOUT.5 128.93,45.36 ; VOUT.5 130.34,43.96 ; VOUT.5 128.93,42.55
  L4_PWR w0.35: J1.2 74.94,27.16 ; J1.2 74,26.23 ; J1.2 74,28.1 ; J1.2 73.06,27.16 ; P6.2 16.99,69.92 ; P6.2 15.8,68.73 ; P6.2 15.8,71.11 ; P6.2 14.61,69.92 ; 19.44,58.2 TP_AGND.1 ; TP_AGND.1 20.5,59.26 ; TP_AGND.1 20.5,57.14
  L5_GND w0.35: TP_PGND.1 53.66,72.42 ; TP_PGND.1 51.54,72.42 ; TP_PGND.1 52.6,73.48 ; TP_PGND.1 52.6,71.36 ; VOUT_BUFF.2 130.34,38.04 ; VOUT_BUFF.2 127.53,38.04 ; VOUT_BUFF.2 128.93,39.44 ; VOUT_BUFF.2 128.93,36.63 ; 67.92,72.42 TP_AGND2.1 ; TP_AGND2.1 70.05,72.42 ; TP_AGND2.1 68.98,71.36 ; TP_AGND2.1 68.98,73.48 ; J1.2 74,28.1 ; J1.2 73.06,27.16 ; J1.2 74,26.23 ; J1.2 74.94,27.16 ; 15.8,68.73 P6.2 ; P6.2 16.99,69.92 ; P6.2 14.61,69.92 ; P6.2 15.8,71.11 ; 134.01,47.63 VOUT.3 ; VOUT.3 134.01,50.44 ; VOUT.3 132.61,49.04 ; VOUT_BUFF.3 134.01,39.44 ; VOUT_BUFF.3 134.01,36.63 ; VOUT_BUFF.3 132.61,38.04 ; VOUT.5 128.93,45.36 ; VOUT.5 127.53,43.96 ; VOUT.5 130.34,43.96 ; VOUT.5 128.93,42.55 ; J9.2 74,43.1 ; J9.2 74,41.23 ; J9.2 73.06,42.16 ; J9.2 74.94,42.16 ; 127.53,49.04 VOUT.2 ; VOUT.2 128.93,47.63 ; VOUT.2 128.93,50.44 ; VOUT.2 130.34,49.04 ; 20.5,57.14 TP_AGND.1 ; TP_AGND.1 20.5,59.26 ; TP_AGND.1 19.44,58.2 ; TP_AGND.1 21.56,58.2 ; VOUT_BUFF.4 134.01,34.36 ; VOUT_BUFF.4 134.01,31.55 ; VOUT_BUFF.4 132.61,32.95 ; 127.53,32.95 VOUT_BUFF.5 ; VOUT_BUFF.5 130.34,32.95 ; VOUT_BUFF.5 128.93,34.36 ; VOUT_BUFF.5 128.93,31.55 ; 132.61,43.96 VOUT.4 ; VOUT.4 134.01,42.55 ; VOUT.4 134.01,45.36
  BOTTOM w0.35: 51.54,72.42 TP_PGND.1 ; TP_PGND.1 52.6,73.48 ; TP_PGND.1 52.6,71.36 ; TP_PGND.1 53.66,72.42 ; 132.61,32.95 VOUT_BUFF.4 ; VOUT_BUFF.4 134.01,31.55 ; VOUT_BUFF.4 134.01,34.36 ; J9.2 74,43.1 ; J9.2 74.94,42.16 ; J9.2 73.06,42.16 ; J9.2 74,41.23 ; 19.44,58.2 TP_AGND.1 ; TP_AGND.1 20.5,59.26 ; TP_AGND.1 20.5,57.14 ; TP_AGND.1 21.56,58.2 ; VOUT.2 128.93,50.44 ; VOUT.2 128.93,47.63 ; VOUT.2 130.34,49.04 ; VOUT.2 127.53,49.04 ; 127.53,32.95 VOUT_BUFF.5 ; VOUT_BUFF.5 128.93,31.55 ; VOUT_BUFF.5 128.93,34.36 ; VOUT_BUFF.5 130.34,32.95 ; TP_AGND2.1 68.98,73.48 ; TP_AGND2.1 70.05,72.42 ; TP_AGND2.1 67.92,72.42 ; TP_AGND2.1 68.98,71.36 ; 134.01,42.55 VOUT.4 ; VOUT.4 134.01,45.36 ; VOUT.4 132.61,43.96 ; VOUT_BUFF.2 130.34,38.04 ; VOUT_BUFF.2 128.93,36.63 ; VOUT_BUFF.2 127.53,38.04 ; VOUT_BUFF.2 128.93,39.44 ; VOUT.5 130.34,43.96 ; VOUT.5 128.93,45.36 ; VOUT.5 128.93,42.55 ; VOUT.5 127.53,43.96 ; P6.2 15.8,71.11 ; P6.2 15.8,68.73 ; P6.2 16.99,69.92 ; P6.2 14.61,69.92 ; 132.61,49.04 VOUT.3 ; VOUT.3 134.01,47.63 ; VOUT.3 134.01,50.44 ; J1.2 74.94,27.16 ; J1.2 74,26.23 ; J1.2 73.06,27.16 ; J1.2 74,28.1 ; 132.61,38.04 VOUT_BUFF.3 ; VOUT_BUFF.3 134.01,39.44 ; VOUT_BUFF.3 134.01,36.63
  vias: v1(3.81,63.81) v1(3.81,53.81) v1(3.81,33.81) v1(8.81,48.81) v1(8.81,38.81) v1(8.81,28.81) v1(8.81,18.81) v1(8.81,8.81) v1(13.81,73.81) v1(13.81,53.81) v1(13.81,43.81) v1(13.81,33.81) v1(13.81,23.81) v1(13.81,13.81) v1(13.81,3.81) v1(15.5,60.43) v1(18.1,61.82) v1(18.81,48.81) v1(18.81,38.81) v1(18.81,28.81) v1(18.81,18.81) v1(18.81,8.81) v1(23.81,73.81) v1(23.81,53.81) v1(23.81,43.81) v1(23.81,33.81) v1(23.81,23.81) v1(23.81,13.81) v1(23.81,3.81) v1(25.5,60.43) v1(28.1,61.82) v1(28.81,68.81) v1(28.81,58.81) v1(28.81,48.81) v1(28.81,38.81) v1(28.81,28.81) v1(28.81,18.81) v1(28.81,8.81) v1(33.81,73.81) v1(33.81,63.81) v1(33.81,53.81) v1(33.81,43.81) v1(33.81,33.81) v1(33.81,23.81) v1(33.81,13.81) v1(33.81,3.81) v1(38.81,68.81) v1(38.81,48.81) v1(38.81,38.81) v1(38.81,28.81) v1(38.81,18.81) v1(38.81,8.81) v1(41.46,59.88) v1(41.46,58.88) v1(41.46,57.88) v1(42.31,55.71) v1(42.46,59.88) v1(42.46,57.88) v1(43.46,59.88) v1(43.46,58.88) v1(43.46,57.88) v1(43.81,73.81) v1(43.81,43.81) v1(43.81,33.81) v1(43.81,23.81) v1(43.81,13.81) v1(43.81,3.81) v1(44.48,53.81) v1(46.26,49.25) v1(48.81,48.81) v1(48.81,38.81) v1(48.81,28.81) v1(48.81,18.81) v1(48.81,8.81) v1(49.06,56.1) v1(52.66,55.05) v1(53.81,73.81) v1(53.81,53.81) v1(53.81,43.81) v1(53.81,33.81) v1(53.81,23.81) v1(53.81,13.81) v1(53.81,3.81) v1(55.73,73.8) v1(58.59,73.8) v1(58.81,48.81) v1(58.81,38.81) v1(58.81,28.81) v1(58.81,18.81) v1(58.81,8.81) v1(59.86,54.3) v1(62.26,65.8) v1(63.81,73.81) v1(63.86,70.91) v1(63.81,43.81) v1(63.81,33.81) v1(63.81,23.81) v1(63.81,13.81) v1(63.81,3.81) v1(65.06,54.3) v1(67.86,67.2) v1(67.86,65.6) v1(68.3,57.49) v1(68.66,66.4) v1(68.81,48.81) v1(68.81,38.81) v1(68.81,28.81) v1(68.81,18.81) v1(68.81,8.81) v1(69.46,67.2) v1(69.46,65.6) v1(69.76,52.75) v1(71.33,69.11) v1(73.81,73.81) v1(73.81,33.81) v1(73.81,13.81) v1(74.87,61.74) v1(75.95,65.33) v1(78.79,72.42) v1(78.81,68.81) v1(78.81,48.81) v1(78.81,38.81) v1(78.81,28.81) v1(78.81,18.81) v1(78.81,8.81) v1(83.81,43.81) v1(83.81,33.81) v1(83.81,23.81) v1(85.59,34.75) v1(88.31,31.78) v1(88.81,58.81) v1(88.81,18.81) v1(89.81,31.78) v1(90.17,45.91) v1(90.36,50.27) v1(92.01,30.11) v1(92.01,28.61) v1(92.21,37.23) v1(93.81,53.81) v1(98.81,58.81) v1(99.58,41.79) v1(101.86,48.81) v1(103.81,53.81) v1(106.99,47.86) v1(107.18,52.21) v1(107.66,33.51) v1(108.31,40.61) v1(108.81,58.81) v1(108.81,48.81) v1(110.21,45.14) v1(110.23,34) v1(111.71,45.14) v1(112.78,35.79) v1(113.21,45.14) v1(113.81,33.81) v1(117.7,51.6) v1(118.81,58.81) v1(118.81,48.81) v1(121.41,47.64) v1(121.41,46.14) v1(122.38,38.83) v1(124.92,37.45) v1(125.32,51.6) v1(128.81,58.81) v1(133.81,53.81)
DGND: length 138.6
  TOP w0.35: P5.5 133.65,20.38 ; P5.5 133.65,18.12 ; P5.5 132.52,19.25 ; P5.5 134.78,19.25 ; P3.7 126.38,14.5 ; P3.7 127.51,13.37 ; P3.7 125.26,13.37 ; P3.7 126.38,12.24 ; P5.11 137.32,19.25 ; P5.11 136.19,20.38 ; P5.11 135.06,19.25 ; P5.11 136.19,18.12 ; 108.49,61.63 P2.7 ; P2.7 109.62,62.76 ; P2.7 110.75,61.63 ; P2.7 109.62,60.5 ; P2.6 112.16,62.76 ; P2.6 112.16,60.5 ; P2.6 113.29,61.63 ; P2.6 111.03,61.63 ; 91.44,72.42 TP_DGND.1 ; TP_DGND.1 92.5,73.48 ; TP_DGND.1 93.57,72.42 ; TP_DGND.1 92.5,71.36
  TOP w0.5: R6.2 99.9,25.36 ; R6.2 R5.2 ; R6.2 v1(99.21,26.36) ; R5.2 99.9,23.79 ; R5.2 R4.2 ; C1.1 111.37,24.05 ; C1.1 110.11,24.05 ; C1.1 v1(110.74,23.36) ; R4.2 v1(99.21,21.21) ; R4.2 99.9,22.21
  L2_GND w0.35: P2.6 112.16,62.76 ; P2.6 111.03,61.63 ; P2.6 113.29,61.63 ; P2.6 112.16,60.5 ; 132.52,19.25 P5.5 ; P5.5 133.65,18.12 ; P5.5 133.65,20.38 ; P5.5 134.78,19.25 ; P2.7 110.75,61.63 ; P2.7 108.49,61.63 ; P2.7 109.62,60.5 ; P2.7 109.62,62.76 ; P3.7 126.38,14.5 ; P3.7 127.51,13.37 ; P3.7 126.38,12.24 ; P3.7 125.26,13.37 ; TP_DGND.1 92.5,73.48 ; TP_DGND.1 91.44,72.42 ; TP_DGND.1 93.57,72.42 ; TP_DGND.1 92.5,71.36 ; P5.11 137.32,19.25 ; P5.11 136.19,20.38 ; P5.11 136.19,18.12 ; P5.11 135.06,19.25
  L3_SIG w0.35: 136.19,20.38 P5.11 136.19,18.12 ; P2.6 112.16,62.76 ; P2.6 113.29,61.63 ; P2.6 112.16,60.5 ; P2.6 111.03,61.63 ; TP_DGND.1 93.57,72.42 ; TP_DGND.1 91.44,72.42 ; TP_DGND.1 92.5,73.48 ; TP_DGND.1 92.5,71.36 ; P2.7 110.75,61.63 ; P2.7 108.49,61.63 ; P2.7 109.62,60.5 ; P2.7 109.62,62.76 ; 125.26,13.37 P3.7 ; P3.7 127.51,13.37 ; P3.7 126.38,14.5 ; P5.5 133.65,20.38 ; P5.5 133.65,18.12 ; P5.5 132.52,19.25
  L5_GND w0.35: P2.6 112.16,62.76 ; P2.6 112.16,60.5 ; P2.6 113.29,61.63 ; P2.6 111.03,61.63 ; 136.19,18.12 P5.11 ; P5.11 137.32,19.25 ; P5.11 136.19,20.38 ; P5.11 135.06,19.25 ; TP_DGND.1 93.57,72.42 ; TP_DGND.1 91.44,72.42 ; TP_DGND.1 92.5,73.48 ; TP_DGND.1 92.5,71.36 ; 108.49,61.63 P2.7 ; P2.7 109.62,62.76 ; P2.7 110.75,61.63 ; P2.7 109.62,60.5 ; 125.26,13.37 P3.7 ; P3.7 126.38,14.5 ; P3.7 127.51,13.37 ; P3.7 126.38,12.24 ; P5.5 133.65,20.38 ; P5.5 133.65,18.12 ; P5.5 134.78,19.25 ; P5.5 132.52,19.25
  BOTTOM w0.35: P2.6 112.16,62.76 ; P2.6 113.29,61.63 ; P2.6 112.16,60.5 ; P2.6 111.03,61.63 ; 132.52,19.25 P5.5 ; P5.5 133.65,20.38 ; P5.5 134.78,19.25 ; P5.5 133.65,18.12 ; P3.7 127.51,13.37 ; P3.7 126.38,14.5 ; P3.7 125.26,13.37 ; P3.7 126.38,12.24 ; TP_DGND.1 93.57,72.42 ; TP_DGND.1 91.44,72.42 ; TP_DGND.1 92.5,73.48 ; TP_DGND.1 92.5,71.36 ; 108.49,61.63 P2.7 ; P2.7 109.62,62.76 ; P2.7 109.62,60.5 ; P2.7 110.75,61.63 ; 135.06,19.25 P5.11 ; P5.11 137.32,19.25 ; P5.11 136.19,18.12 ; P5.11 136.19,20.38
  vias: v1(82.69,72.42) v1(83.81,73.81) v1(83.81,63.81) v1(83.81,13.81) v1(83.81,3.81) v1(88.81,68.81) v1(88.81,8.81) v1(93.81,73.81) v1(93.81,63.81) v1(93.81,3.81) v1(98.19,12.07) v1(98.81,68.81) v1(98.81,18.81) v1(98.81,8.81) v1(99.58,39.19) v1(100.21,21.21) v1(103.66,20.49) v1(103.81,73.81) v1(103.81,63.81) v1(103.81,3.81) v1(107.24,24.18) v1(108.81,68.81) v1(108.81,28.81) v1(108.81,8.81) v1(109.64,12.07) v1(113.81,73.81) v1(113.81,63.81) v1(113.81,3.81) v1(118.81,68.81) v1(118.81,28.81) v1(118.76,14.97) v1(123.81,73.81) v1(123.81,63.81) v1(123.81,23.81) v1(123.81,3.81) v1(128.81,68.81) v1(128.81,28.81) v1(128.81,8.81) v1(133.81,73.81) v1(133.81,63.81) v1(138.81,68.81) v1(138.81,58.81) v1(138.81,48.81) v1(138.81,38.81) v1(138.81,8.81)
VDD: length 18.3
  TOP w0.5: v1(92.16,39.64) C7.1 93.16,39.84 94.92,39.84 ; C22.1 v1(108.06,41.96) ; v1(119.36,44.75) C27.1 ; C17.1 v1(85.84,40.01)
  L4_PWR w0.35: 76.79,64.3 LK2.2 ; LK2.2 77.92,65.42 ; LK2.2 79.05,64.3 ; LK2.2 77.92,63.17 ; 81.65,58.26 TP_VDD.1 ; TP_VDD.1 82.71,57.2 ; TP_VDD.1 83.77,58.26 ; TP_VDD.1 82.71,59.32 ; J9.1 74.94,39.62 ; J9.1 74,38.69 ; J9.1 74,40.56 ; J9.1 73.06,39.62
  vias: v1(93.61,34.71) v1(109.41,37.11) v1(125.21,43.28)
VSS: length 18.3
  TOP w0.5: U1.18 102.53,41.14 102.73,41.34 v1(103.53,41.34) ; C22.2 v1(108.06,45.56) ; C17.2 v1(85.84,43.61) ; C27.2 v1(115.76,44.75)
  L4_PWR w0.35: 74,43.77 74,44.71 ; 74,44.71 73.06,44.71 ; 74,44.71 74.94,44.71 ; 74,44.71 74,45.64 ; 82.71,53.06 TP_VSS.1 ; TP_VSS.1 81.65,54.12 ; TP_VSS.1 83.77,54.12 ; TP_VSS.1 82.71,55.19 ; LK3.2 77.92,56.31 ; LK3.2 79.05,55.19 ; LK3.2 76.79,55.19 ; LK3.2 77.92,54.06
  vias: v1(86.22,48.47) v1(103.06,50.41) v1(111.11,39.51)
ARD_5V: length 80.7
  TOP w0.2: R14.2 45.47,55.45 v1(45.31,55.61)
  L4_PWR w0.35: 110.89,53.12 LK1.2 ; LK1.2 111.95,54.19 ; LK1.2 110.89,55.25 ; LK1.2 109.83,54.19 ; 48.81,49.45 TP_5V.1 ; TP_5V.1 49.87,50.51 ; TP_5V.1 47.75,50.51 ; TP_5V.1 48.81,51.57
  BOTTOM w0.5: LK1.2 107.19,54.19 105.81,52.81 81.96,52.81 79.66,50.51 TP_5V.1 47.11,50.51 45.31,52.31 v1(45.31,55.61)
ARD_CLRB: length 112.8
  TOP w0.25: R11.2 v1(97.65,35.34) 97.65,36.76 95.87,38.54 U1.7
  L3_SIG w0.2: P4.3 97.94,9.81 135.41,9.81 138.91,13.31 138.91,28.41 136.71,30.61 135.71,30.61 135.01,29.91 135.01,26.41 136.19,25.23 P5.9
  L3_SIG w0.25: P4.3 96.41,15.4 96.41,34.11 95.51,35.01 95.51,35.61 95.91,36.01 96.97,36.01 v1(97.65,35.34)
  BOTTOM w0.25: P4.3 CLRB.1
ARD_LDACB: length 97
  TOP w0.25: R10.2 v1(96.15,35.38) 96.15,37.56 95.82,37.89 U1.8
  L3_SIG w0.2: P4.4 96.92,11.85 98.46,10.31 135.31,10.31 138.41,13.41 138.41,27.19 P5.7
  L3_SIG w0.25: v1(96.15,35.38) 96.92,34.61 P4.4
  BOTTOM w0.25: LDACB.1 96.92,8.46 P4.4
ARD_RESETB: length 87.3
  TOP w0.25: R12.2 v1(99.15,35.34) 99.15,35.96 95.92,39.19 U1.6
  L3_SIG w0.2: P5.8 137.91,25.15 137.91,13.61 135.11,10.81 109.64,10.81 P4.8
  L3_SIG w0.25: P4.8 107.08,20.54 98.35,29.27 98.35,32.65 99.15,33.45 v1(99.15,35.34)
  BOTTOM w0.25: RESETB.1 107.06,13.35 P4.8
ARD_SCL: length 29.1
  TOP w0.2: U3.6 v1(110.24,22.51)
  BOTTOM w0.2: P3.10 131.37,16 125.22,16 118.7,22.51 v1(110.24,22.51)
ARD_SCLK: length 63.8
  TOP w0.25: v1(102.28,37.94) 102.22,37.89 U1.13
  L3_SIG w0.25: v1(102.28,37.94) 102.68,37.94 102.91,37.71 102.91,36.31 101.81,35.21 101.21,35.21 100.81,34.81 100.81,33.01 100.01,32.21 100.01,29.71 113.61,16.11 121.1,16.11 P3.6 123.84,13.44 132.19,21.79 P5.4
  BOTTOM w0.25: SCLK.1 123.84,7.38 P3.6
ARD_SDA: length 26
  TOP w0.2: U3.5 v1(110.24,21.24)
  BOTTOM w0.2: v1(110.24,21.24) 119.3,21.24 124.94,15.6 129.23,15.6 P3.9
ARD_SDIN: length 81.3
  TOP w0.25: 100.78,37.23 v1(102.28,37.23)
  L3_SIG w0.2: P3.4 118.76,13.26 120.71,11.31 134.91,11.31 137.41,13.81 137.41,22.51 136.91,23.01 135.81,23.01 134.91,23.91 134.91,25.61 P5.2
  L3_SIG w0.25: P3.4 117.02,15.11 113.21,15.11 99.01,29.31 99.01,32.61 99.81,33.41 99.81,35.21 101.84,37.23 v1(102.28,37.23)
  BOTTOM w0.25: P3.4 118.76,7.38 SDIN.1
ARD_SDO: length 73.7
  TOP w0.25: v1(102.28,36.53) 102.22,36.59 U1.11
  L3_SIG w0.2: P3.5 122.86,11.81 134.71,11.81 135.61,12.71 135.61,14.71 135.01,15.31 135.01,23.11 133.79,24.33 P5.3
  L3_SIG w0.25: P3.5 121.3,13.42 119.11,15.61 113.41,15.61 99.51,29.51 99.51,32.41 100.31,33.21 100.31,35.01 101.83,36.53 v1(102.28,36.53)
  BOTTOM w0.25: P3.5 SDO.1
ARD_SYNCB: length 56.1
  TOP w0.25: R8.2 R7.2 v1(116.22,19.07) ; U1.14 99.82,38.54 99.5,38.21 99.5,36.32 100.65,35.17 R9.2 v1(101.45,34.59)
  L3_SIG w0.25: v1(101.45,34.59) 101.31,34.45 101.31,29.21 111.45,19.07 v1(116.22,19.07) 117.01,19.07 SYNCB.1 127.35,29.41 P5.1
ARD_VLOGIC: length 54
  TOP w0.25: 94.92,37.23 94.14,37.23 93.81,36.91 93.81,36.11 94.41,35.51 C6.1 C8.1 ; U1.10 94.92,31.2 95.31,30.81 95.31,29.51 C8.1 ; C8.1 v1(94.41,27.61)
  TOP w0.5: R1.1 R2.1 R3.1 v1(95.76,26.36) ; TP_VLOGIC.1 129.39,55.73 C4.1 ; v1(125.32,57.33) C4.1 ; C4.1 125.32,55.7 124.55,54.93 122.32,54.93 E1.2 ; R10.1 R11.1 R12.1 R9.1 v1(100.65,31.88) ; U3.8 C1.2 v1(110.74,25.75)
  L4_PWR w0.35: P5.6 133.65,17.84 ; P5.6 132.52,16.71 ; P5.6 133.65,15.58 ; P5.6 134.78,16.71 ; 136.19,15.58 P5.12 ; P5.12 136.19,17.84 ; P5.12 137.32,16.71 ; P5.12 135.06,16.71
  BOTTOM w0.5: P5.12 P5.6
DAC_INV: length 32.5
  TOP w0.2: U1.1 v1(94.92,43.44)
  TOP w0.25: v1(115.76,37.25) C10.2 116.76,41.16 116.29,41.63 U2.2
  L3_SIG w0.25: v1(115.76,37.25) 109.29,43.71 105.01,43.71 103.81,44.91 96.39,44.91 v1(94.92,43.44)
DAC_VOUT: length 52
  TOP w0.2: U1.20 v1(100.78,43.44)
  TOP w0.25: U2.6 118.86,40.36 118.36,39.86 C10.1 v1(119.36,37.25)
  L3_SIG w0.25: v1(100.78,43.44) 101.75,44.41 103.61,44.41 104.81,43.21 108.91,43.21 115.51,36.61 116.01,36.61 116.64,37.25 v1(119.36,37.25) 121.11,35.49 VOUT_BUFF.1
  BOTTOM w0.5: VOUT_BUFF.1 124.92,35.49 TP_VOUT_BUFF.1
EXT_VDD: length 60.4
  L3_SIG w0.762: v1(25.1,65.62) v1(26.1,65.62) v1(27.1,65.62) v1(28.1,65.62) 32.69,70.21 58.11,70.21 58.81,69.51 69.19,69.51 71.87,66.83 LK2.3
  L4_PWR w0.35: 25.5,57.14 TP_EXT_VDD.1 ; TP_EXT_VDD.1 25.5,59.26 ; TP_EXT_VDD.1 24.44,58.2 ; TP_EXT_VDD.1 26.56,58.2
EXT_VSS: length 74.8
  L3_SIG w0.762: v1(15.1,65.62) v1(16.1,65.62) v1(17.1,65.62) v1(18.1,65.62) 19.2,65.62 20.81,64.01 29.51,64.01 33.11,67.61 62.41,67.61 63.41,66.61 63.41,64.01 64.41,63.01 71.51,63.01 76.79,57.73 LK3.3
  L4_PWR w0.35: TP_EXT_VSS.1 16.56,58.2 ; TP_EXT_VSS.1 15.5,59.26 ; TP_EXT_VSS.1 14.44,58.2 ; TP_EXT_VSS.1 15.5,57.14
LDO_VDD: length 17.3
  L3_SIG w0.5: TP_LDO_VDD.1 86.75,56.57 81.56,61.76 LK2.1 76.76,61.76 v1(74.87,63.64)
LDO_VSS: length 17.4
  TOP w0.5: R36.2 69.78,55.87 C46.1
  L3_SIG w0.5: v1(70.06,56.85) 74.27,52.65 LK3.1 80.02,52.65 TP_LDO_VSS.1
REF_VREFN: length 39
  TOP w0.2: v1(104.39,42.66) U8.5
  BOTTOM w0.5: v1(104.39,42.66) 93.56,42.66 89.21,38.31 89.21,34.91 83.96,29.66 79.79,29.66 TP_VREFN.1 J1.3
REF_VREFP: length 35
  TOP w0.2: v1(87.56,38.31) U7.5
  BOTTOM w0.5: TP_VREFP.1 J1.1 73,24.62 71.81,25.81 71.81,30.81 72.86,31.86 83.76,31.86 87.56,35.66 v1(87.56,38.31)
UNNAMED_3_CAP_I64_N1: length 8.9
  TOP w0.5: LK1.1 E2.2 114.7,54.93 116.89,54.93 C5.1
UNNAMED_3_CN8PA_I4_N2: length 3
  TOP w0.5: P2.2 E1.1
UNNAMED_3_CN8PA_I4_N5: length 3
  TOP w0.5: P2.5 E2.1
UNNAMED_3_CN10P_I1_N2: length 3
  TOP w0.2: R8.1 P3.2
UNNAMED_3_CN10P_I1_N3: length 3
  TOP w0.2: R7.1 P3.3
UNNAMED_3_IC24XX32AV2_I22_A0: length 7.2
  TOP w0.25: U3.1 v1(101.66,25.05) 101.36,25.36 R6.1 ; R3.2 v1(98.21,25.37)
  L3_SIG w0.2: v1(101.66,25.05) 99.08,25.05 98.76,25.37 v1(98.21,25.37)
UNNAMED_3_IC24XX32AV2_I22_A1: length 6.9
  TOP w0.25: R2.2 v1(98.21,23.79) ; R5.1 v1(101.66,23.79) U3.2
  L3_SIG w0.2: v1(101.66,23.79) v1(98.21,23.79)
UNNAMED_3_IC24XX32AV2_I22_A2: length 7.2
  TOP w0.25: R4.1 101.36,22.21 v1(101.66,22.51) U3.3 ; R1.2 v1(98.21,22.21)
  L3_SIG w0.2: v1(101.66,22.51) 99.06,22.51 98.76,22.21 v1(98.21,22.21)
UNNAMED_4_AD5781_I1_VOUT: length 57.7
  TOP w0.2: U1.2 93.92,41.79 93.62,42.09 v1(93.62,43.44)
  TOP w0.25: U2.3 v1(113.57,40.36)
  L3_SIG w0.25: v1(93.62,43.44) 95.59,45.41 104.01,45.41 105.21,44.21 109.72,44.21 v1(113.57,40.36) 118.26,40.36 124.39,46.5 VOUT.1
  BOTTOM w0.5: TP_VOUT.1 124.92,46.5 VOUT.1
UNNAMED_5_ADP5070_I35_COMP1: length 3.9
  TOP w0.25: R26.1 C35.1 39.8,60.8 40.44,60.16 U4.6
UNNAMED_5_ADP5070_I35_COMP2: length 4
  TOP w0.25: U4.10 40.44,57.54 39.86,56.96 C37.1 R27.1
UNNAMED_5_ADP5070_I35_EN1: length 17
  TOP w0.25: U4.7 39.78,59.38 v1(39.36,59.8) ; v1(39.36,57.88) 39.86,58.38 U4.9 ; v1(47.16,52.45) R15.2 R14.1
  L3_SIG w0.25: v1(47.16,52.45) 44.27,52.45 39.36,57.36 v1(39.36,57.88) v1(39.36,59.8)
UNNAMED_5_ADP5070_I35_FB1: length 7
  TOP w0.25: U4.5 40.4,60.9 39.51,61.79 39.51,64.8 R25.1 R24.1
UNNAMED_5_ADP5070_I35_FB2: length 3.6
  TOP w0.25: R29.1 R28.2 40.05,55.95 40.2,56.1 41.1,56.1 41.46,56.46 U4.11
UNNAMED_5_ADP5070_I35_SEQ: length 5.9
  TOP w0.2: R22.1 v1(42.46,65.25)
  TOP w0.25: U4.3 v1(42.46,61.9) R19.2
  L3_SIG w0.25: v1(42.46,65.25) v1(42.46,61.9)
UNNAMED_5_ADP5070_I35_SLEW: length 6.7
  TOP w0.2: R21.1 v1(40.96,65.25)
  TOP w0.25: U4.4 41.96,61.56 41.62,61.9 v1(40.96,61.9) R18.2
  L3_SIG w0.25: v1(40.96,65.25) v1(40.96,61.9)
UNNAMED_5_ADP5070_I35_SS: length 1.9
  TOP w0.25: U4.8 R16.2
UNNAMED_5_ADP5070_I35_SW2: length 3.3
  TOP w0.25: U4.18 47.78,58.88
UNNAMED_5_ADP5070_I35_SYNC: length 6.6
  TOP w0.2: R20.1 v1(43.96,65.25)
  TOP w0.25: R17.2 v1(43.96,61.9) 43.4,61.9 42.96,61.46 U4.2
  L3_SIG w0.25: v1(43.96,65.25) v1(43.96,61.9)
UNNAMED_5_ADP5070_I35_VREF: length 3.3
  TOP w0.25: C39.1 41.05,54.35 R28.1 41.96,56.27 U4.12
UNNAMED_5_ADP5070_I35_VREG: length 18.9
  TOP w0.2: U4.14 42.96,55.81 C47.1 v1(44.46,55.11) ; R17.1 R19.1 R18.1 v1(40.16,64.35)
  L3_SIG w0.25: v1(40.16,64.35) 40.16,57.26 41.01,56.41 43.16,56.41 v1(44.46,55.11)
UNNAMED_5_ADP7118V3_I94_EN: length 3.2
  L3_SIG w0.5: v1(64.79,68.31) v1(64.79,65.13)
UNNAMED_5_ADP7182V5_I95_ADJ: length 5.2
  TOP w0.2: U6.2 71.06,57.24 71.39,56.91 72.89,56.91 73.31,56.49 R36.1 R35.2
UNNAMED_5_ADP7182V5_I95_EN:
  vias: v1(70.56,58.81) v1(71.56,58.81)
UNNAMED_5_CAP_I61_N1: length 23.2
  TOP w0.25: R24.2 v1(37.41,66.3)
  L3_SIG w0.25: v1(37.41,66.3) v1(59.89,66.3)
UNNAMED_5_CAP_I69_N1: length 1.4
  TOP w0.25: C36.1 R26.2
UNNAMED_5_CAP_I73_N1: length 1.4
  TOP w0.25: R27.2 C38.1
UNNAMED_5_CAP_I79_N1: length 30.3
  TOP w0.25: R29.2 v1(40.05,52.64)
  L3_SIG w0.25: v1(66.46,58.6) 59.67,51.81 40.88,51.81 v1(40.05,52.64)
UNNAMED_5_CN3P_I3_N1: length 4.8
  TOP w0.35: 19.61,69.92 P6.1 ; P6.1 20.8,71.11 ; P6.1 20.8,68.73 ; P6.1 21.99,69.92
UNNAMED_5_CN3P_I3_N3: length 4.8
  TOP w0.35: P6.3 11.98,69.92 ; P6.3 10.79,71.11 ; P6.3 9.6,69.92 ; P6.3 10.79,68.73
VREFNF: length 12.6
  TOP w0.2: 105.46,39.61 105.69,39.84 U8.7 ; 105.46,39.61 C12.1 ; 105.46,39.61 105.46,35.41 TP_VREFN_BUFF.1
  TOP w0.25: 100.78,39.84 102.23,39.84 102.46,39.61 C12.1
VREFNS: length 5.1
  TOP w0.2: U8.6 105.04,40.74 104.78,40.48 U1.17
VREFPF: length 12.4
  TOP w0.2: TP_VREFP_BUFF.1 88.51,37.01 88.86,37.36 U7.7 88.86,40.27 89.07,40.48 C11.1 U1.4
VREFPS: length 8.2
  TOP w0.2: U7.6 88.2,40.21 88.21,40.21 88.21,40.61 88.91,41.31 93.61,41.31 93.78,41.14 U1.3

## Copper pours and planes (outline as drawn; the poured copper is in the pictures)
AGND on TOP: 0.5,74.5 80.5,74.5 80.5,59.5 135.51,59.5 135.51,31.31 125.11,31.31 102.41,31.31 102.11,31.61 102.11,40.61 93.91,40.61 93.91,16.4 80.5,16.4 80.5,0.5 0.5,0.5 ; 4 cut-outs
AGND on BOTTOM: 0.5,74.5 80.5,74.5 80.5,59.5 135.51,59.5 135.51,31.31 102.41,31.31 102.11,31.61 102.11,40.61 93.91,40.61 93.91,16.4 80.5,16.4 80.5,0.5 0.5,0.5
AGND on L2_GND: 0.5,74.5 80.5,74.5 80.5,59.5 135.51,59.5 135.51,31.31 102.41,31.31 102.11,31.61 102.11,40.61 93.91,40.61 93.91,16.4 80.5,16.4 80.5,0.5 0.5,0.5
AGND on L4_PWR: 0.5,74.5 32.21,74.5 32.21,29.01 93.61,29.01 93.61,20.31 125.41,20.31 125.41,0.5 0.5,0.5
AGND on L5_GND: 0.5,74.5 80.5,74.5 80.5,59.5 135.51,59.5 135.51,31.31 102.41,31.31 102.11,31.61 102.11,40.61 93.91,40.61 93.91,16.41 80.5,16.41 80.5,0.5 0.5,0.5
DGND on TOP: 81.01,74.5 139.5,74.5 139.5,0.5 81.01,0.5 81.01,15.91 94.41,15.91 94.41,40.11 101.61,40.11 101.61,31.41 102.21,30.81 136.01,30.81 136.01,60 81.01,60 ; 3 cut-outs
DGND on BOTTOM: 81,74.5 139.5,74.5 139.5,0.5 81,0.5 81,15.91 94.41,15.91 94.41,40.11 101.61,40.11 101.61,31.41 102.21,30.81 136.01,30.81 136.01,60 81,60
DGND on L2_GND: 81,74.5 139.5,74.5 139.5,0.5 81,0.5 81,15.91 94.41,15.91 94.41,40.11 101.61,40.11 101.61,31.41 102.21,30.81 136.01,30.81 136.01,60 81,60
DGND on L3_SIG: 0.5,74.5 139.5,74.5 139.5,0.5 0.5,0.5
DGND on L5_GND: 81,74.5 139.5,74.5 139.5,0.5 81,0.5 81,15.91 94.41,15.91 94.41,40.11 101.61,40.11 101.61,31.41 102.21,30.81 136.01,30.81 136.01,60 81,60
VDD on TOP: 106.17,42.12 106.17,36.82 109.66,36.82 109.66,37.56 109.11,38.11 109.11,38.63 107.75,38.63 107.17,39.21 107.17,40.4 107.01,40.56 107.01,42.12
VDD on TOP: 89.31,40.11 89.31,33.91 93.91,33.91 93.91,35.41 91.91,35.41 91.51,35.81 91.51,36.81 90.18,38.14 90.18,40.11
